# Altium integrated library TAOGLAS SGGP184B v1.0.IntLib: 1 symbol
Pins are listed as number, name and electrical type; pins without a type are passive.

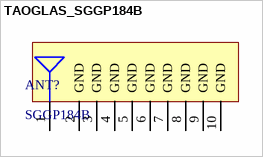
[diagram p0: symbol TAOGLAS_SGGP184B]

## TAOGLAS_SGGP184B
designator ANT?, comment SGGP184B
GPS/GLONASS/GALILEO Dual-Band 18*18*4mm Ceramic Patch SMD Antenna; ComponentLibStatus: Created; MFG: Taoglas; Temp_High: +85C; Temp_Low: -40C
footprint TAOGLAS_SGGP184B (GPS/GLONASS/GALILEO Dual-Band 18*18*4mm Ceramic Patch SMD Antenna)
pins: 1 RF FEED, 2 GND, 3 GND, 4 GND, 5 GND, 6 GND, 7 GND, 8 GND, 9 GND, 10 GND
